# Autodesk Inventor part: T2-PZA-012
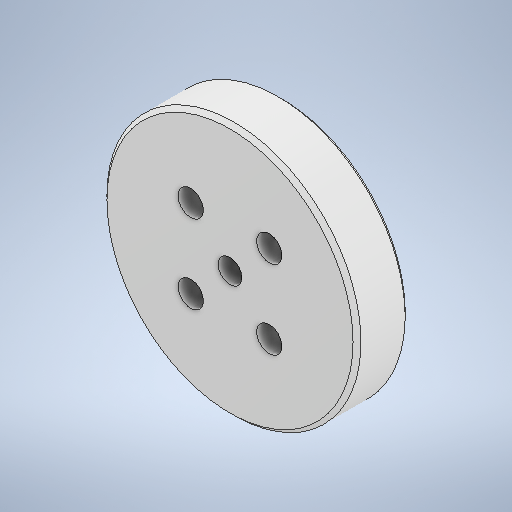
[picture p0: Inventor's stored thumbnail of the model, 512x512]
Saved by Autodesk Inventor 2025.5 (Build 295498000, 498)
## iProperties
Created: 2026-10
Part Number: T2-PZA-012
Material: Genérico
Description: Leva de accionamiento
Document SubType Name: Modeling
Designer: Luis MuÃ±oz
Density: 1 g/cm^3
Appearance: Valor por defecto
Project: TESIS 2 - Plataforma mecatrÃ³nica preventiva desacoplada
Sending System: ONSHAPE BY PTC INC, 1.194
Preprocessor: ST-DEVELOPER v20
Material_Fabricacion: PLA
Title: Leva de accionamiento
Revision Number: 00
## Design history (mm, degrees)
feature "Cam"
sketch "Boceto1"
  geometry: C1 r 27.731 at (17.32, 1.065); 1 further point
  constraints: 1 centre point
extrude "Extrusión1" cut sketch "Boceto1" distance "d0" = 10; taper "d1" = 0 deg
node "Sólido1"
